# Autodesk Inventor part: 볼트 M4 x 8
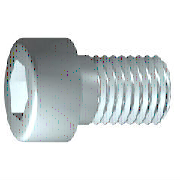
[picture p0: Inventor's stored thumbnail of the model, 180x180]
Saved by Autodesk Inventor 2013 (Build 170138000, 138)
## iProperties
IsCustomPart: 1
Created: 2012-02
Part Number: 볼트 M4 x 8
Material: 스테인리스강
Description: 6각 소켓 머리 캡 나사
Document SubType Name: Modeling
Standard: ISO 4762
Designer: mduedu
Standard Revision: Fourth edition 2004-03-01
Standards Organization: ISO
Language: ko-KR
Size Designation: M4 x 8
Categories: <MemberInstance><Categories><Category DisplayName="조임쇠" InternalName="e4da775c-781d-43d5-af7c-5136215cf5a6" Mnemonic="FSTN"><Category DisplayName="볼트" InternalN
Density: 7.75 g/cm^3
Author: mduedu
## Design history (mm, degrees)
sketch "스케치1"
  geometry: L1 (-1, 0)-(8, 0); L2 (8, 0)-(8, 2); L3 (8, 2)-(1.75, 2); L4 (1.75, 2)-(1.32, 2); L5 (1.32, 2)-(0, 2); L6 (0, 2)-(0, 3.5); L7 (0, 3.5)-(-4, 3.5); L8 (-4, 3.5)-(-4, 1.732); L9 (-4, 1.732)-(-2, 1.732); L10 (-2, 1.732)-(-1, 0); L11 (-6.4, 0)-(10.4, 0) reference; L12 (0, -0.7)-(0, 4.2) reference; L13 (1.75, 2)-(0, 2)
  constraints: 22 end point, 6 parallel, 2 collinear, 2 perpendicular, 1 horizontal, 1 point on line
  dimensions: "d1" = 6.25 distance from line of L3.end L2 (= GEL); "d2" = 0.42952 distance of L4.end L3.end (computed from GAL); "d3" = 4 distance between parallel lines of L8 L6 (= KOH); "d4" = 2 distance of L8.end L9.end (= INTI); "d5" = 60 deg angle of L10 L1; "d6" = 4 diameter of L3 L1 (= GD); "d7" = 4 diameter of L5 L1 (= BDM); "d8" = 3.4641 diameter of L9 L1 (= 1.1547 x SW); "d9" = 7 diameter of L7 L1 (= KOD); "d26" = 8 distance between parallel lines of L12 L2 (= NLG)
revolve "본체" sketch "스케치1" stored, may be unused: angle "d10" = 90 deg
sketch "스케치2"
  geometry: L1 (0, -4.9)-(0, 4.9) reference; L2 (-4.9, 0)-(4.9, 0) reference; L3 (1.732, 0)-(0.866, -1.5); L4 (0.866, -1.5)-(-0.866, -1.5); L5 (-0.866, -1.5)-(-1.732, 0); L6 (-1.732, 0)-(-0.866, 1.5); L7 (-0.866, 1.5)-(0.866, 1.5); L8 (0.866, 1.5)-(1.732, 0); 2 further points
  constraints: 12 end point, 1 coincident, 1 horizontal alignment, 1 point on line, 12 other
extrude "슬롯" join sketch "스케치2" stored distance "d11" = 10; taper "d12" = 0 deg
workplane "Work Plane1"
fillet "Fillet2" dims "d30" = 0.1 (= R)
body "Solid1"
fillet "모깎기1" dims "d17" = 0.4 (= RR)
feature "스레드" dims "d13" = 6.25 (= GEL), "d14" = 0
chamfer "모따기1" distance "d15" = 0.42941 (= -0.5 x SPD + 0.5 x GD); stored, may be unused: second distance "d16" = 0.42941 (= GUL), angle "d27" = 45 deg
other parameters: "GD" = 4 [user parameter; used in 2 equation terms], "NLG" = 8 [user parameter; used in 1 equation term], "GEL" = 6.25 [user parameter; used in 2 equation terms], "KOD" = 7 [user parameter; used in 1 equation term], "KOH" = 4 [user parameter; used in 1 equation term], "INTI" = 2 [user parameter; used in 1 equation term], "GAL" = 0.42941 (= 0.61345 x PTC) [user parameter; used in 1 equation term], "GUL" = 0.42941 (= 0.61345 x PTC) [user parameter; used in 1 equation term], "BDM" = 4 (= NND) [user parameter; used in 1 equation term], "SW" = 3 [user parameter; used in 2 equation terms], "RR" = 0.4 [user parameter; used in 1 equation term], "SPD" = 3.14117 (= NND - 1.2269 x PTC) [user parameter; used in 1 equation term], "d19" = 0, "d28" = 0, "d29" = 0, "R" = 0.1 [user parameter; used in 1 equation term], "TOA" = 30 deg [user parameter], "GD1" = 3.14117 (= THREADDIA - 1.2269 x PTC) [user parameter], "THREADDIA" = 4 [user parameter; used in 1 equation term], "FAWI" = 45 deg [user parameter], "TPU" = 14.28571 (computed from PTC) [user parameter], "PTC" = 0.7 [user parameter; used in 5 equation terms], "NND" = 4 [user parameter; used in 2 equation terms], "E0" = 3.465 (= 1.155 x SW) [user parameter]
